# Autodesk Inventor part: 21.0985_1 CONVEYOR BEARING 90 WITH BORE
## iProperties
Created: 2007-07
Part Number: 21.0985_1 CONVEYOR BEARING 90 WITH BORE
Document SubType Name: Modeling
Designer: Andy Moles
Material: Aluminum-6061
Mass: 704.1 g
Surface Area: 722.944 cm^2
Volume: 259.815 cm^3
Density: 2.71 g/cm^3
Author: Andy Moles
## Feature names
1. Extrusion1
2. Extrusion2
3. Hole1
4. Chamfer1
5. Extrusion3
6. Fillet1
7. Extrusion4
8. Extrusion5
9. Mirror1
10. Extrusion6
11. Extrusion7
12. Extrusion8
13. Extrusion9
14. Extrusion10
15. Extrusion11
16. Extrusion12
17. Mirror2
18. Extrusion13
